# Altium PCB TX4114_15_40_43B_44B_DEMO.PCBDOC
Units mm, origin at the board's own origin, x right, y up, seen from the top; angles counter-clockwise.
Board outline 48.26 x 30 mm, 2 copper layers (Top Layer, Bottom Layer); 16 components, 8 nets, 42 pads, 42 vias.
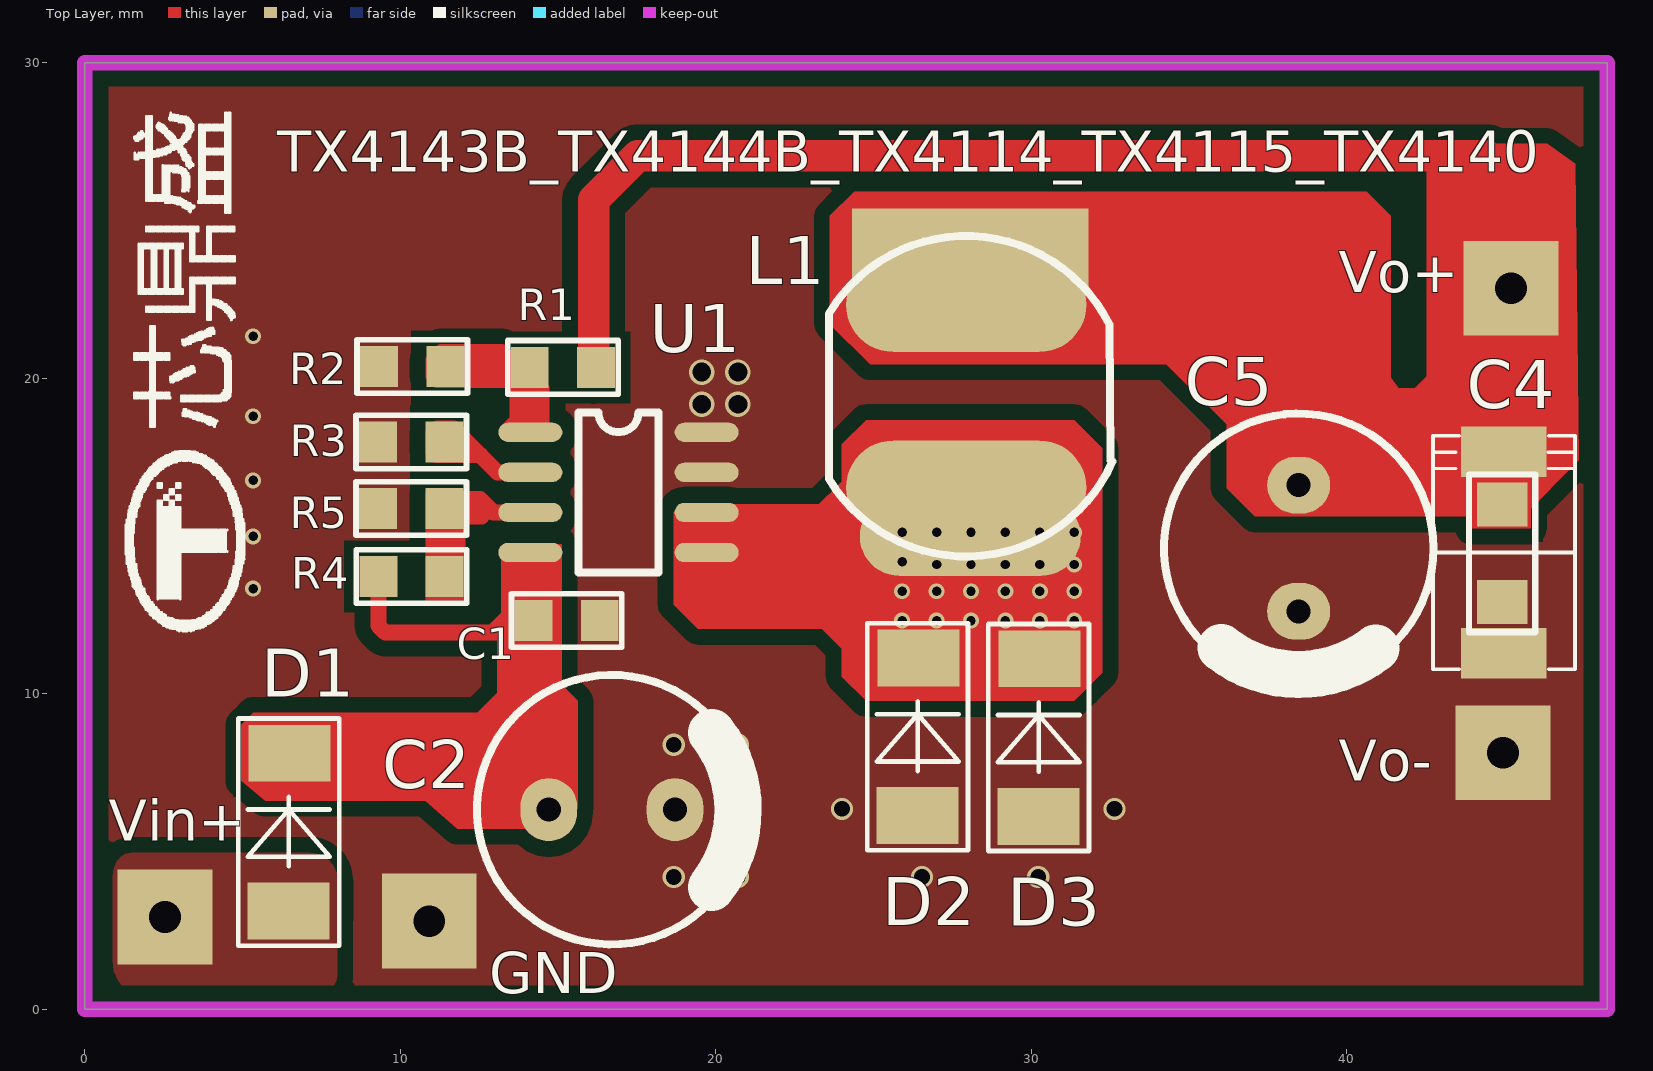
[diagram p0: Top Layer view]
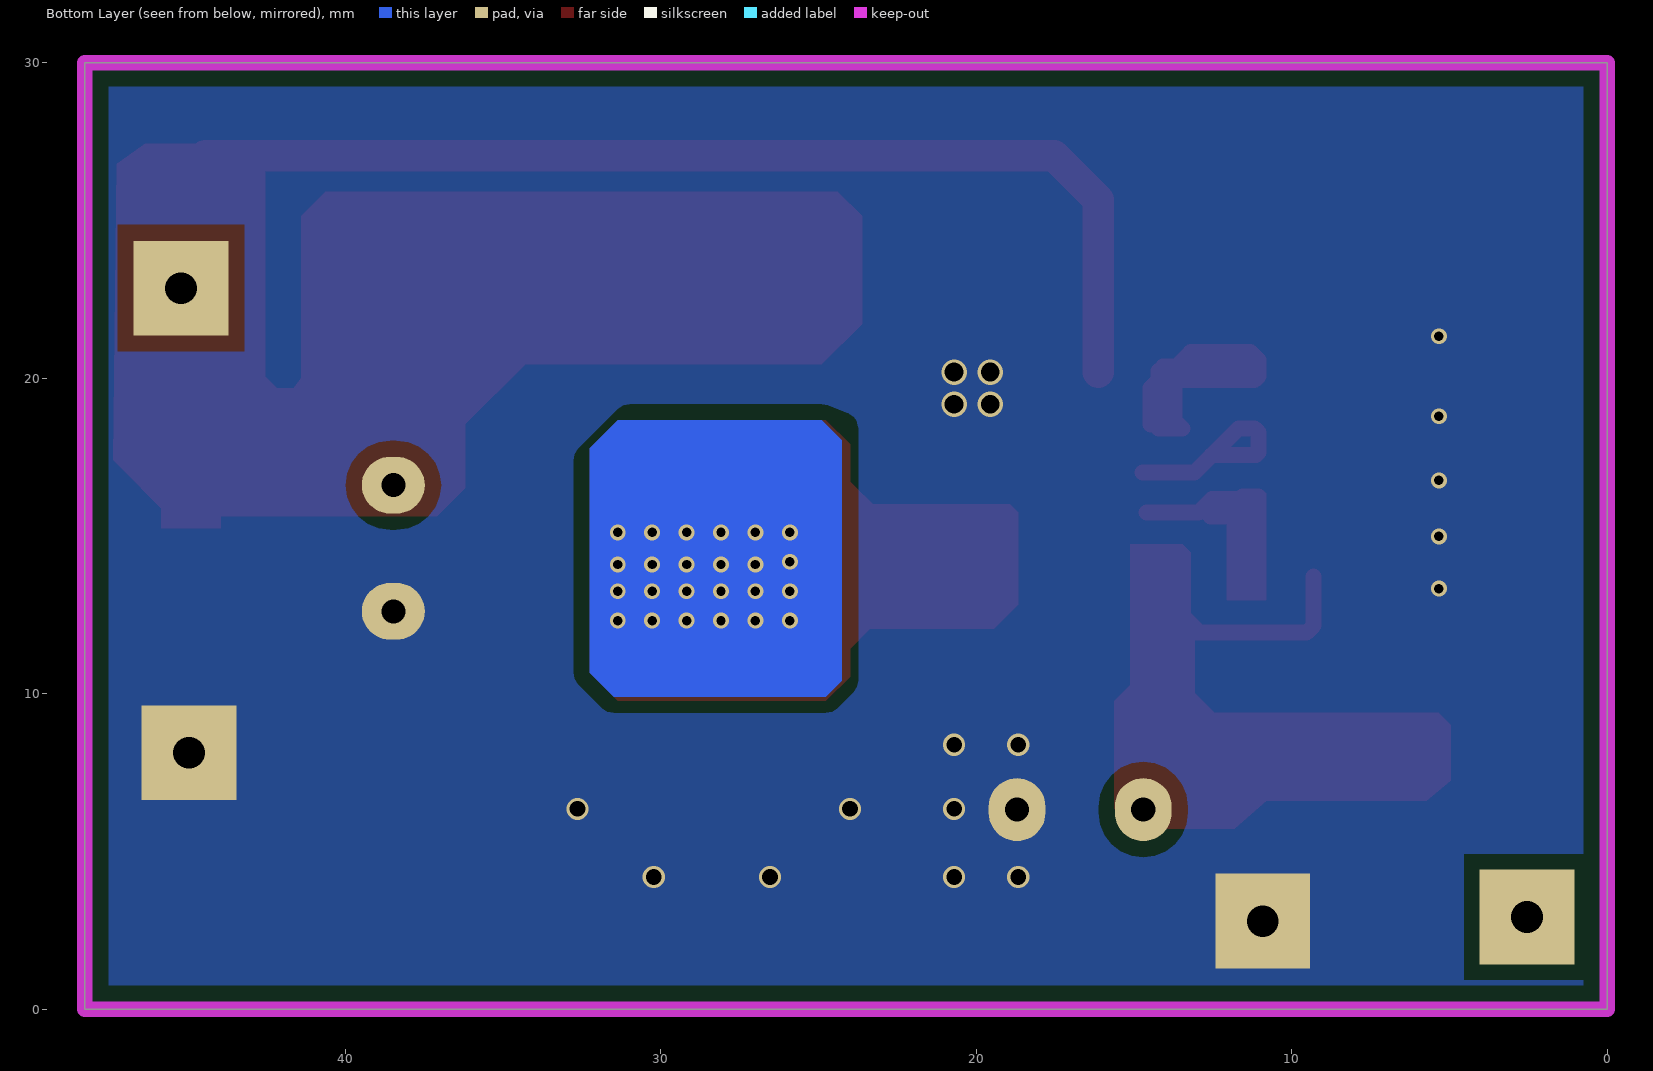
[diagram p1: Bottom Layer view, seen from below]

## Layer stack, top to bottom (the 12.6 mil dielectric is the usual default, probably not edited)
Top Layer: signal copper 0.0356
Dielectric: dielectric 0.32, FR-4, Dk 4.8
Bottom Layer: signal copper 0.0356

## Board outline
0,0 48.26,0 48.26,30 0,30

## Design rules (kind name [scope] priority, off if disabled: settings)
Clearance [All] p1: gap=0.5
ComponentClearance [All] p1 off: gap=0.254 collisioncheckmode=3 verticalgap=0.254 showdistances=FALSE
Height [All] p1 off: minheight=0 maxheight=25.4 prefheight=12.7
PlaneConnect [All] p1: planeconnectstyle=Direct reliefexpansion=0.508 reliefentries=4 reliefconductorwidth=0.254 reliefairgap=0.254
PolygonConnect [All] p1: connectstyle=Direct reliefconductorwidth=0.254 reliefentries=4 polygonreliefangle="90 Angle"
RoutingVias [All] p1: holewidth=0.711 width=1.27 viastyle="Through Hole" minholewidth=0.711 minwidth=1.27 maxholewidth=0.711 maxwidth=1.27
SilkscreenOverComponentPads SilkToSolderMaskClearance [IsPad] p1: minsilkscreentomaskgap=0.254
SolderMaskExpansion [All] p1: expansion=0.102
TestPointUsage [All] p1: valid=0 allowmultiple=FALSE
Testpoint [All] p1: side=3 testpointundercomponent=TRUE minsize=1.016 maxsize=2.54 preferedsize=1.524 minholesize=0 maxholesize=1.016 preferedholesize=0.813 testpointgrid=0.025 style=297 order=0-112345678
Width [All] p1: maxlimit=5.08 minlimit=0.508 preferedwidth=0.508
20 further rules are at their usual default settings.

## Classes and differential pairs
component class OC5820-0902原理图: C1 C2 C3 C4 C5 D1 D2 D3 D54 R1 R2 R3 R4 R5 U1

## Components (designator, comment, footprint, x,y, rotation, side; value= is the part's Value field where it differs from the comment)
C1 "CAP" 0805R 14.224,12.319 r0 top
C2 "" C8*12 14.707,6.325 r270 top (schematic designator C5)
C4 "" 1206R 44.933,14.453 r90 top
C5 "" C8*12 38.481,16.612 r180 top
D1 "DIODE" SMB 6.477,5.613 r90 top
D2 "" SMB 26.416,8.636 r90 top
D3 "" SMB 30.251,8.611 r90 top
L1 "" CD105 27.94,19.431 r0 top
R1 "" 0805R 16.205,20.345 r180 top
R2 "" 0805R 11.43,20.371 r180 top
R3 "" 0805R 9.296,17.983 r0 top
R4 "" 0805R 11.405,13.716 r180 top
R5 "" 0805R 9.296,15.875 r0 top
U1 "" SO-8 14.122,18.288 r0 top
? "Comment" LOGO 2.667,14.859 r90 top
? "Comment" 7343 44.983,14.478 r0 top

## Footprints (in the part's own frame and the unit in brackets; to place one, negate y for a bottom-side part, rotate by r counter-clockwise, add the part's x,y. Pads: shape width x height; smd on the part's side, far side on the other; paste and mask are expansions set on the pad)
0805R [mm]
  rect 1.2x1.3 smd: 1(0,0) 2(2.1,0)
  silkscreen extent -0.7,-0.85 2.8,0.85
1206R [mm]
  rect 1.4x1.6 smd: 1(1.55,0) 2(-1.55,0)
  silkscreen extent -2.5,-1.05 2.5,1.05
7343 [mm]
  rect 2.7x1.6 smd: 1(0,3.2) 2(0,-3.2)
  silkscreen extent -2.25,-3.7 2.25,3.7
C8*12 [mm]
  oval 2x1.8 hole 0.762: 1(0,0) 2(0,4)
  silkscreen extent -4.27,-2.27 4.27,6.27
CD105 [mm]
  oval 7.62x3 smd: 1(0,-2.9) 2(0,2.9)
  silkscreen extent -4.36,-5.08 4.64,5.08
LOGO [mm]
  silkscreen extent -2.88,-2.39 13.56,1.37
SMB [mm]
  rect 1.8x2.6 smd: 1(-2.5,0.016) 2(2.5,-0.016)
  silkscreen extent -3.6,-1.58 3.6,1.62
SO-8 [mil]
  oval 80x24 smd: 1(0,0) 2(0,-50) 3(0,-100) 4(0,-150) 5(220,-150) 6(220,-100) 7(220,-50) 8(220,0)
  silkscreen extent 60,-175 160,25

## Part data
C1: "Capacitor"
C2 C5: library part CAPACITOR, "Capacitor"
C4: library part CAP, "Capacitor"
D1: "Diode"
D2 D3: library part DIODE, "Diode"
L1: library part INDUCTOR
R1 R2 R3 R4 R5: library part RES1_1
U1: library part "HEADER 4X2"

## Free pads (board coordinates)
  rect 3x3 hole 1: 0(2.54,2.921) 0(10.922,2.794) 0(44.958,8.128) 0(45.212,22.86)
  oval 7x2.5 smd: 0(28.067,14.986)
  rect 7.5x2.5 smd: 0(28.067,24.13)

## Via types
v1: diameter 0.5, hole 0.3, Top Layer to Bottom Layer, 29 vias
v2: diameter 0.7, hole 0.5, Top Layer to Bottom Layer, 9 vias
v3: diameter 0.8, hole 0.6, Top Layer to Bottom Layer, 4 vias

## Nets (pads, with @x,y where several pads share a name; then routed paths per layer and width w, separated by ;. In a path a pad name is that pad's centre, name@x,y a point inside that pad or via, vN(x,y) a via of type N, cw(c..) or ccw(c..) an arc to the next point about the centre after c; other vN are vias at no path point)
GND: ?.2 C1.2 C2.2 C4.2 C5.2 D2.1 D3.1 pad.0@10.922,2.794 pad.0@44.958,8.128 R2.2 R3.1 R5.1 U1.7 U1.8
  other v1: 5.334,13.335 5.334,14.986 5.334,16.764 5.334,18.796 5.334,21.336
  other v2: 18.669,4.191 20.701,4.191 26.543,4.191 30.226,4.191 20.701,6.35 24.003,6.35 32.639,6.35 18.669,8.382 20.701,8.382
  other v3: 19.558,19.177 20.701,19.177 19.558,20.193 20.701,20.193
NetC1_1: C1.1 C2.1 D1.2 R4.2 U1.4 | length 6.9
  Top Layer w0.508: R4.2 9.305,12.158 9.525,11.938 14.097,11.938 14.097,12.192 C1.1
NetC3_1: ?.1 C4.1 C5.1 L1.2 pad.0@28.067,24.13 pad.0@45.212,22.86 R1.1 | length 35.8
  Top Layer w0.508: L1.2@27.432,22.352 27.697,22.087 L1.2@28.448,21.336
  Top Layer w1: R1.1@16.129,20.193 16.129,20.345 16.129,25.654 17.526,27.051 44.45,27.051
NetC3_2: R1.2 R2.1 U1.1 | length 16
  Top Layer w0.508: R2.1 14.08,20.371 14.224,20.227 14.224,18.415 13.462,18.415 13.716,18.669 13.716,20.244 13.843,20.371 13.665,20.371 13.208,20.828 11.303,20.828 11.049,20.574 11.049,20.066 11.176,19.939 13.589,19.939 13.716,20.066 14.097,20.066 14.224,19.939 14.478,19.685 U1.1@14.478,18.542
NetD2_2: D2.2 D3.2 L1.1 pad.0@28.067,14.986 U1.5 U1.6 | length 2.4
  Top Layer w0.508: 23.241,15.621 L1.1@24.257,16.637 ; L1.1@27.284,15.875 L1.1
  other v1: 25.908,12.319 27,12.319 28.092,12.319 29.185,12.319 30.277,12.319 31.369,12.319 25.908,13.25 27,13.25 28.092,13.25 29.185,13.25 30.277,13.25 31.369,13.25 27,14.097 28.092,14.097 29.185,14.097 30.277,14.097 31.369,14.097 25.908,14.182 25.908,15.113 27,15.113 28.092,15.113 29.185,15.113 30.277,15.113 31.369,15.113
NetU1_3: R4.1 R5.2 U1.3 | length 7.6
  Top Layer w0.508: R5.2 12.634,15.875 12.73,15.972 ; U1.3@14.605,15.748 U1.3 12.954,15.748 12.73,15.972 ; 12.73,15.972 12.73,15.778 12.573,15.621 11.396,15.621 11.303,15.621 11.223,15.701 11.176,15.748 11.176,15.875 11.176,16.129 11.049,16.256 11.396,16.256 11.557,16.256 11.635,16.178 12.524,16.178 12.73,15.972
NetU1_4: R3.2 U1.2 | length 6.5
  Top Layer w0.508: U1.2@14.732,17.018 U1.2 13.081,17.018 12.536,17.563 ; 12.536,17.563 11.396,17.563 11.139,17.563 11.058,17.644 11.049,17.653 11.049,17.983 11.049,18.288 11.07,18.309 11.176,18.415 11.396,18.415 11.684,18.415 11.756,18.343 12.536,17.563
VCC: D1.1 pad.0@2.54,2.921

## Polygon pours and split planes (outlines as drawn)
VCC on Top Layer "Top Layer-No Net" (solid, remove dead copper, pour order 1002): 0.889,2.921 0.889,1.555 ccw(c2.19,1.555) 1.27,0.635 ccw(c1.577,0.942) 1.577,0.508 4.191,0.508 7.261,0.508 ccw(c7.261,1.375) 7.874,0.762 ccw(c7.567,1.069) 8.001,1.069 8.001,1.524 8.001,4.086 ccw(c7.134,4.086) 7.747,4.699 ccw(c7.134,4.086) 7.134,4.953 2.921,4.953 1.45,4.953 ccw(c1.45,4.519) 1.143,4.826 ccw(c1.756,4.213) 0.889,4.213 0.889,2.921
GND on Top Layer "Top Layer-No Net" (solid, remove dead copper, pour order 1003): 47.616,29.718 -0.644,29.718 -0.263,29.337 -0.263,-0.536 47.616,-0.536 47.87,-0.282 48.124,-0.028 48.124,29.563
GND on Bottom Layer "Top Layer-No Net" (solid, remove dead copper, pour order 1004): 48.26,0.508 48.26,29.845 48.514,30.099 48.387,29.972 0.254,29.972 0.254,0.254 48.514,0.254

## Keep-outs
Keep-Out Layer:
  the board outline again, w0.5

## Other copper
Top Layer:
  region net NetC3_1: 45.847,15.24 45.847,18.034 43.942,18.034 43.942,15.24
  region net NetU1_3: 12.065,12.954 12.065,16.383 10.795,16.383 10.795,12.954
  region net NetC3_1: 23.622,25.146 23.622,21.717 24.892,20.447 34.29,20.447 36.195,18.542 36.195,16.51 37.084,15.621 45.593,15.621 47.366,17.394 47.244,26.797 46.355,27.432 42.545,27.432 42.545,20.066 42.164,19.685 41.656,19.685 41.402,20.024 41.402,25.146 40.64,25.908 24.384,25.908
  region net NetC1_1: 13.462,14.732 15.113,14.732 15.113,11.811 14.986,11.684 14.859,11.811 13.716,11.811 13.208,12.319 13.208,14.478
  region net NetD2_2: 24.765,18.669 31.369,18.669 32.258,17.78 32.258,10.668 31.369,9.779 24.765,9.779 24.003,10.541 24.003,17.907
  region net NetD2_2: 18.923,16.002 18.669,15.748 18.669,12.827 19.431,12.065 23.368,12.065 24.003,11.43 25.019,11.43 25.019,16.002
  region net NetC1_1: 4.953,9.017 4.953,7.239 5.715,6.604 10.795,6.604 11.811,5.715 14.986,5.715 15.621,6.35 15.621,9.779 15.113,10.287 15.113,11.811 13.97,12.954 13.335,12.954 13.335,12.7 12.827,12.192 13.081,11.938 13.081,10.033 12.446,9.398 5.334,9.398
Bottom Layer:
  region net NetD2_2: 24.257,18.034 24.257,10.414 24.765,9.906 31.496,9.906 32.258,10.668 32.258,17.78 31.369,18.669 24.892,18.669

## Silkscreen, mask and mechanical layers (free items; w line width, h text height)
Top Overlay:
  text "TX4143B_TX4144B_TX4114_TX4115_TX4140" at 6.096,26.543 h1.3
  text "Vo+" at 39.751,22.733 h1.3
  text "Vo-" at 39.751,7.239 h1.3
  text "Vin+" at 0.756,5.343 h1.3
  text "GND" at 12.827,0.508 h1.3
Top Solder:
  rectangle: 24.892,14.478 31.496,15.875
Bottom Solder:
  region: 21.082,11.811 21.082,20.828 14.859,20.828 14.859,11.811
  region: 31.75,10.414 31.75,18.034 24.765,18.034 24.765,10.414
